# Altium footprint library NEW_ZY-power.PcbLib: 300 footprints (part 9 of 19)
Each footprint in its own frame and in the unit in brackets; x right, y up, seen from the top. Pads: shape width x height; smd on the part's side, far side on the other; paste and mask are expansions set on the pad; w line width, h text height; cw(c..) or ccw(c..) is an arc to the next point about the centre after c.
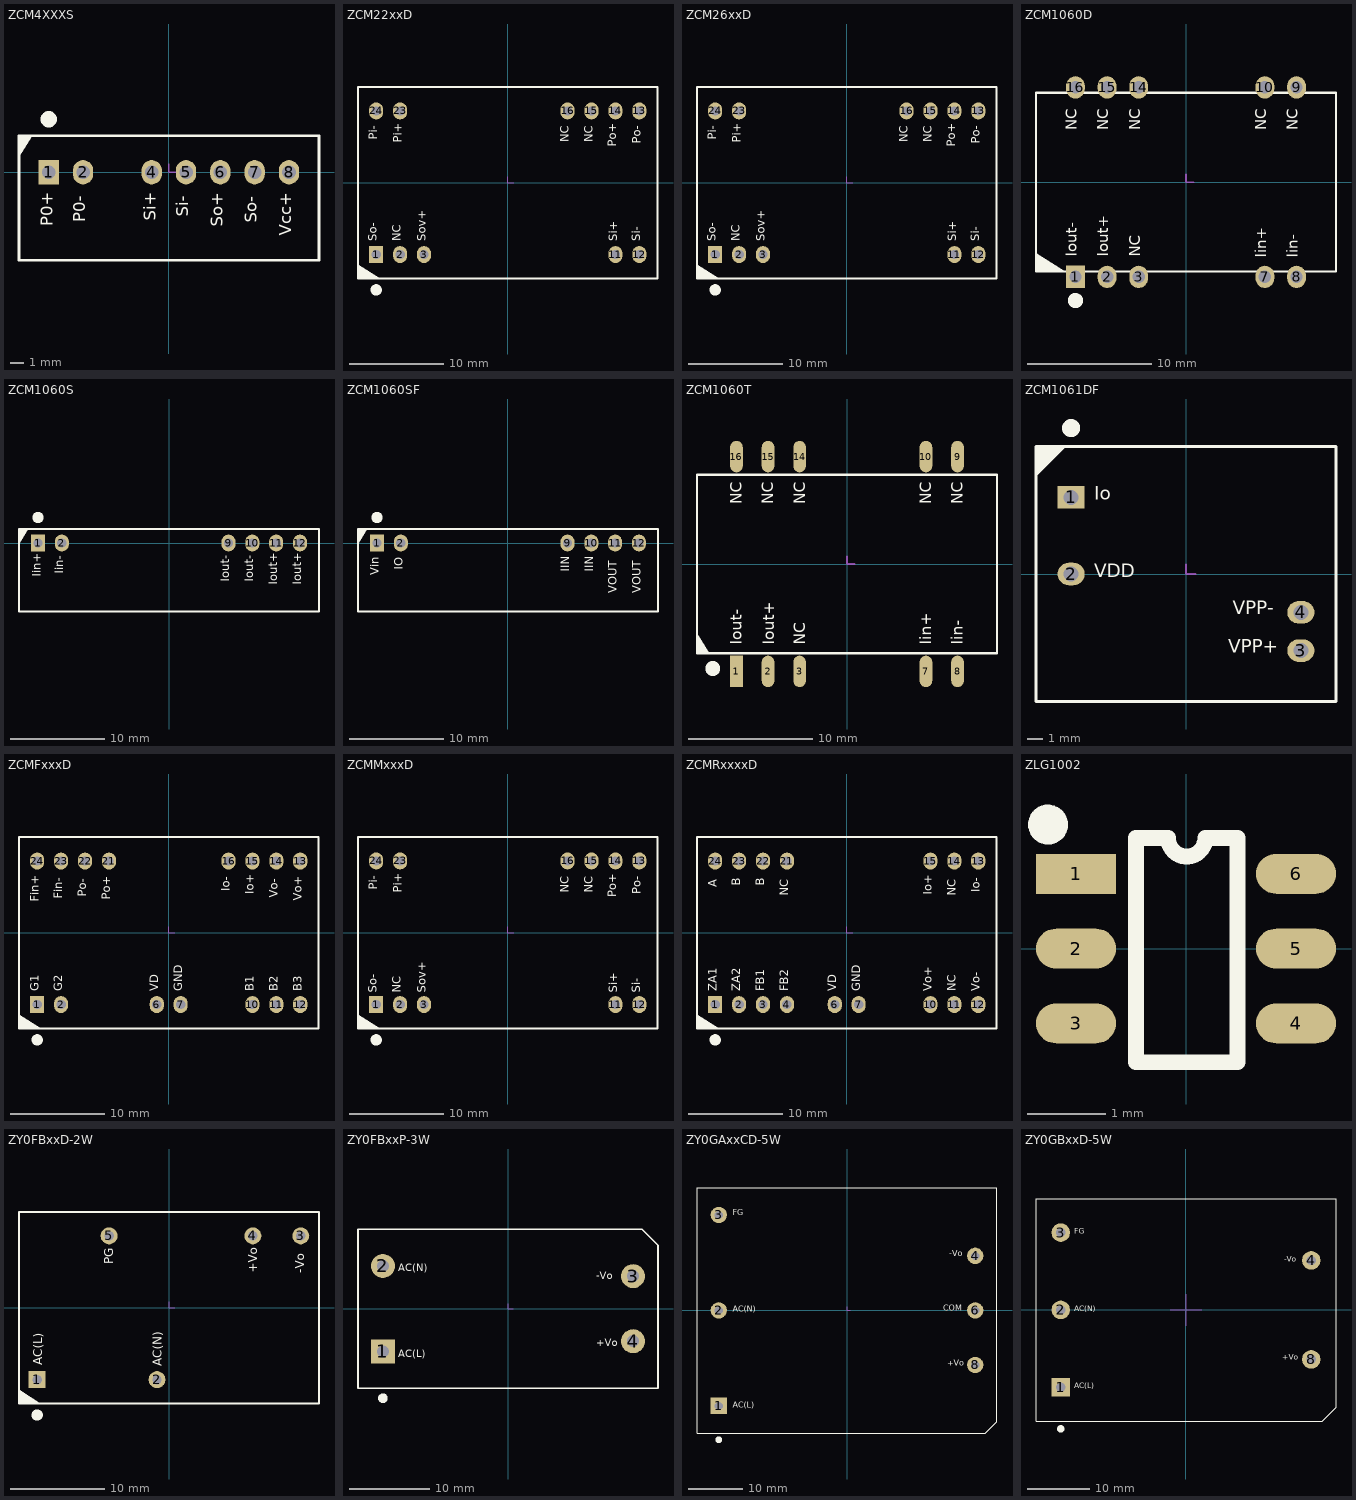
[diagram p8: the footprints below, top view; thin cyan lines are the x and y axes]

## ZCM4XXXS [mm]
pads (7):
  rect 1.5x1.8 hole 1: 1(-8.89,0)
  oval 1.5x1.8 hole 1: 2(-6.35,0) 4(-1.27,0) 5(1.27,0) 6(3.81,0) 7(6.35,0) 8(8.89,0)
Top Overlay:
  circle w1: c-8.89,3.925 r0.1
  region: -11.09,1.114 -11.09,2.7 -10.096,2.7
  lines w0.2: -11.09,-6.5 11.11,-6.5 11.11,2.7 -11.09,2.7 -11.09,-6.5
  text "Vcc+" at 9.357,-4.699 h1.52
  text "So-" at 6.817,-3.727 h1.52
  text "So+" at 4.277,-4.036 h1.52
  text "Si-" at 1.737,-3.273 h1.52
  text "Si+" at -0.676,-3.582 h1.52
  text "P0-" at -5.883,-3.684 h1.52
  text "P0+" at -8.296,-3.993 h1.52
Mechanical 15:
  lines w0.127: 0,0.635 0,0 0.635,0

## ZCM22xxD [mm]
height 9.5
pads (11):
  rect 1.5x1.8 hole 1: 1(-13.97,-7.62)
  oval 1.5x1.8 hole 1: 2(-11.43,-7.62) 3(-8.89,-7.62) 11(11.43,-7.62) 12(13.97,-7.62) 13(13.97,7.62) 14(11.43,7.62) 15(8.89,7.62) 16(6.35,7.62) 23(-11.43,7.62) 24(-13.97,7.62)
Top Overlay:
  circle w1: c-13.97,-11.375 r0.1
  region: -13.57,-10.15 -15.9,-10.15 -15.9,-8.69
  lines w0.2: -15.9,-10.15 15.9,-10.15 15.9,10.15 -15.9,10.15 -15.9,-10.15
  text "Po+" at 11.836,3.81 h1.52
  text "Pi+" at -10.922,4.265 h1.52
  text "Pi-" at -13.513,4.574 h1.52
  text "Sov+" at -8.382,-6.223 h1.52
  text "NC" at -11.049,-6.223 h1.52
  text "Si+" at 11.938,-6.223 h1.52
  text "So-" at -13.589,-6.223 h1.52
  text "Si-" at 14.402,-6.223 h1.52
  text "Po-" at 14.427,4.119 h1.52
  text "NC" at 9.322,4.281 h1.52
  text "NC" at 6.782,4.281 h1.52
Mechanical 15:
  lines w0.127: 0,0.635 0,0 0.635,0

## ZCM26xxD [mm]
height 9.5
pads (11):
  rect 1.5x1.8 hole 1: 1(-13.97,-7.62)
  oval 1.5x1.8 hole 1: 2(-11.43,-7.62) 3(-8.89,-7.62) 11(11.43,-7.62) 12(13.97,-7.62) 13(13.97,7.62) 14(11.43,7.62) 15(8.89,7.62) 16(6.35,7.62) 23(-11.43,7.62) 24(-13.97,7.62)
Top Overlay:
  circle w1: c-13.97,-11.375 r0.1
  region: -13.57,-10.15 -15.9,-10.15 -15.9,-8.69
  lines w0.2: -15.9,-10.15 -15.9,10.15 15.9,10.15 15.9,-10.15 -15.9,-10.15
  text "Si-" at 14.402,-6.223 h1.52
  text "So-" at -13.589,-6.223 h1.52
  text "Si+" at 11.938,-6.223 h1.52
  text "NC" at -11.049,-6.223 h1.52
  text "Sov+" at -8.382,-6.223 h1.52
  text "NC" at 6.782,4.281 h1.52
  text "NC" at 9.322,4.281 h1.52
  text "Po-" at 14.427,4.119 h1.52
  text "Pi-" at -13.513,4.574 h1.52
  text "Pi+" at -10.922,4.265 h1.52
  text "Po+" at 11.836,3.81 h1.52
Mechanical 15:
  lines w0.127: 0,0.635 0,0 0.635,0

## ZCM1060D [mm]
height 10
pads (10):
  rect 1.5x1.8 hole 1: 1(-8.89,-7.62)
  oval 1.5x1.8 hole 1: 2(-6.35,-7.62) 3(-3.81,-7.62) 7(6.35,-7.62) 8(8.89,-7.62) 9(8.89,7.62) 10(6.35,7.62) 14(-3.81,7.62) 15(-6.35,7.62) 16(-8.89,7.62)
Top Overlay:
  circle w1: c-8.89,-9.525 r0.1
  region: -9.735,-7.188 -12.065,-7.188 -12.065,-5.728
  lines w0.2: -12.065,-7.188 12.065,-7.188 12.065,7.188 -12.065,7.188 -12.065,-7.188
  text "Iin+" at 6.782,-6.071 h1.52
  text "Iin-" at 9.322,-6.071 h1.52
  text "Iout+" at -5.944,-5.994 h1.52
  text "NC" at -5.918,4.191 h1.52
  text "Iout-" at -8.484,-5.994 h1.52
  text "NC" at -8.458,4.191 h1.52
  text "NC" at -3.378,4.191 h1.52
  text "NC" at 6.782,4.191 h1.52
  text "NC" at 9.322,4.191 h1.52
  text "NC" at -3.353,-6.02 h1.52
Mechanical 15:
  lines w0.127: 0,0.635 0,0 0.635,0

## ZCM1060S [mm]
height 14.8
pads (6):
  rect 1.5x1.8 hole 1: 1(-13.97,0)
  oval 1.5x1.8 hole 1: 2(-11.43,0) 9(6.35,0) 10(8.89,0) 11(11.43,0) 12(13.97,0)
Top Overlay:
  circle w1: c-13.97,2.725 r0.1
  region: -16,-0.086 -16,1.5 -15.006,1.5
  lines w0.2: -16,-7.3 -16,1.5 16,1.5 16,-7.3 -16,-7.3
  text "Iin+" at -13.376,-3.611 h1.52
  text "Iin-" at -10.963,-3.302 h1.52
  text "Iout-" at 6.766,-4.136 h1.52
  text "Iout-" at 9.306,-4.136 h1.52
  text "Iout+" at 11.846,-4.445 h1.52
  text "Iout+" at 14.402,-4.445 h1.52

## ZCM1060SF [mm]
height 14.8
pads (6):
  rect 1.5x1.8 hole 1: 1(-13.97,0)
  oval 1.5x1.8 hole 1: 2(-11.43,0) 9(6.35,0) 10(8.89,0) 11(11.43,0) 12(13.97,0)
Top Overlay:
  circle w1: c-13.97,2.725 r0.1
  region: -16,-0.086 -16,1.5 -15.006,1.5
  lines w0.2: -16,-7.3 -16,1.5 16,1.5 16,-7.3 -16,-7.3
  text "Vin" at -13.46,-3.454 h1.52
  text "IO" at -10.92,-2.833 h1.52
  text "IIN" at 6.86,-3.086 h1.52
  text "IIN" at 9.4,-3.086 h1.52
  text "VOUT" at 11.94,-5.334 h1.52
  text "VOUT" at 14.48,-5.334 h1.52

## ZCM1060T [mil]
height 393.7
pads (10):
  rect 40x100 smd: 1(-350,-340)
  oval 40x100 smd: 2(-250,-340) 3(-150,-340) 7(250,-340) 8(350,-340) 9(350,340) 10(250,340) 14(-150,340) 15(-250,340) 16(-350,340)
Top Overlay:
  circle w39.37: c-425,-331.23 r3.94
  region: -475,-220.58 -475,-283 -435.88,-283
  lines w7.87: -475,-283 475,-283 475,283 -475,283 -475,-283
  text "Iin+" at 267,-255 h36
  text "Iin-" at 367,-255 h36
  text "Iout+" at -230,-255 h36
  text "NC" at -233,190 h36
  text "Iout-" at -334,-255 h36
  text "NC" at -333,190 h36
  text "NC" at -133,190 h36
  text "NC" at 267,190 h36
  text "NC" at 367,190 h36
  text "NC" at -132,-255 h36
Mechanical 15:
  lines w5: 0,25 0,0 25,0

## ZCM1061DF [mm]
height 7.05
pads (4):
  rect 1.8x1.5 hole 1: 1(-7.62,5.08)
  oval 1.8x1.5 hole 1: 2(-7.62,0) 3(7.62,-5.08) 4(7.62,-2.54)
Top Overlay:
  circle w1: c-7.62,9.677 r0.1
  region: -9.95,8.453 -7.975,8.452 -9.95,6.478
  lines w0.2: -9.95,-8.447 -9.95,8.453 9.95,8.453 9.95,-8.447 -9.95,-8.447
  text "VPP+" at 2.794,-5.532 h1.52
  text "VPP-" at 3.103,-2.966 h1.52
  text "Io" at -6.097,4.643 h1.52
  text "VDD" at -6.096,-0.508 h1.52
Mechanical 15:
  lines w0.127: 0,0.635 0,0 0.635,0

## ZCMFxxxD [mm]
pads (15):
  rect 1.5x1.8 hole 1: 1(-13.97,-7.62)
  oval 1.5x1.8 hole 1: 2(-11.43,-7.62) 6(-1.27,-7.62) 7(1.27,-7.62) 10(8.89,-7.62) 11(11.43,-7.62) 12(13.97,-7.62) 13(13.97,7.62) 14(11.43,7.62) 15(8.89,7.62) 16(6.35,7.62) 21(-6.35,7.62) 22(-8.89,7.62) 23(-11.43,7.62) 24(-13.97,7.62)
Top Overlay:
  circle w1: c-13.97,-11.375 r0.1
  region: -13.57,-10.15 -15.9,-10.15 -15.9,-8.69
  lines w0.2: -15.9,-10.15 -15.9,10.15 15.9,10.15 15.9,-10.15 -15.9,-10.15
  text "B3" at 14.437,-6.224 h1.52
  text "B2" at 11.897,-6.224 h1.52
  text "B1" at 9.357,-6.224 h1.52
  text "GND" at 1.737,-6.224 h1.52
  text "VD" at -0.803,-6.223 h1.52
  text "G2" at -10.963,-6.224 h1.52
  text "G1" at -13.503,-6.224 h1.52
  text "Vo+" at 14.437,3.422 h1.52
  text "Vo-" at 11.897,3.731 h1.52
  text "Io+" at 9.357,4.075 h1.52
  text "Io-" at 6.817,4.384 h1.52
  text "Po+" at -5.883,3.522 h1.52
  text "Po-" at -8.423,3.831 h1.52
  text "Fin-" at -10.963,3.611 h1.52
  text "Fin+" at -13.503,3.302 h1.52
Mechanical 15:
  lines w0.127: 0,0.635 0,0 0.635,0

## ZCMMxxxD [mm]
height 9.5
pads (11):
  rect 1.5x1.8 hole 1: 1(-13.97,-7.62)
  oval 1.5x1.8 hole 1: 2(-11.43,-7.62) 3(-8.89,-7.62) 11(11.43,-7.62) 12(13.97,-7.62) 13(13.97,7.62) 14(11.43,7.62) 15(8.89,7.62) 16(6.35,7.62) 23(-11.43,7.62) 24(-13.97,7.62)
Top Overlay:
  circle w1: c-13.97,-11.375 r0.1
  region: -13.57,-10.15 -15.9,-10.15 -15.9,-8.69
  lines w0.2: -15.9,-10.15 -15.9,10.15 15.9,10.15 15.9,-10.15 -15.9,-10.15
  text "NC" at 6.782,4.258 h1.52
  text "NC" at 9.322,4.258 h1.52
  text "Po-" at 14.427,4.096 h1.52
  text "Si-" at 14.402,-6.375 h1.52
  text "So-" at -13.589,-6.375 h1.52
  text "Si+" at 11.938,-6.375 h1.52
  text "NC" at -11.049,-6.375 h1.52
  text "Sov+" at -8.382,-6.375 h1.52
  text "Pi-" at -13.513,4.551 h1.52
  text "Pi+" at -10.922,4.242 h1.52
  text "Po+" at 11.836,3.787 h1.52
Mechanical 15:
  lines w0.127: 0,0.635 0,0 0.635,0

## ZCMRxxxxD [mm]
pads (16):
  rect 1.5x1.8 hole 1: 1(-13.97,-7.62)
  oval 1.5x1.8 hole 1: 2(-11.43,-7.62) 3(-8.89,-7.62) 4(-6.35,-7.62) 6(-1.27,-7.62) 7(1.27,-7.62) 10(8.89,-7.62) 11(11.43,-7.62) 12(13.97,-7.62) 13(13.97,7.62) 14(11.43,7.62) 15(8.89,7.62) 21(-6.35,7.62) 22(-8.89,7.62) 23(-11.43,7.62) 24(-13.97,7.62)
Top Overlay:
  circle w1: c-13.97,-11.375 r0.1
  region: -13.57,-10.15 -15.9,-10.15 -15.9,-8.69
  lines w0.2: -15.9,-10.15 15.9,-10.15 15.9,10.15 -15.9,10.15 -15.9,-10.15
  text "FB1" at -8.423,-6.223 h1.52
  text "FB2" at -5.883,-6.223 h1.52
  text "Vo-" at 14.437,-6.223 h1.52
  text "NC" at 11.897,-6.223 h1.52
  text "Vo+" at 9.357,-6.223 h1.52
  text "GND" at 1.737,-6.223 h1.52
  text "VD" at -0.803,-6.223 h1.52
  text "ZA2" at -10.963,-6.223 h1.52
  text "ZA1" at -13.503,-6.223 h1.52
  text "Io-" at 14.437,4.328 h1.52
  text "NC" at 11.897,3.937 h1.52
  text "Io+" at 9.357,4.019 h1.52
  text "NC" at -5.883,3.937 h1.52
  text "B" at -8.423,5.01 h1.52
  text "B" at -10.963,5.01 h1.52
  text "A" at -13.503,4.836 h1.52
Mechanical 15:
  lines w0.127: 0,0.635 0,0 0.635,0

## ZLG1002 [mil] "ZLG1002"
height 45.28
pads (6):
  rect 40x20 smd: 1(-55,37.4)
  oval 40x20 smd: 2(-55,0) 3(-55,-37.4) 4(55,-37.4) 5(55,0) 6(55,37.4)
Top Overlay:
  circle w10: c-69,62 r5
  lines w7.87: -25,55.4 -25,-56.8 25.7,-56.8 25.7,55.4 ; -9,55.4 ccw(c0.35,55.4) 9.7,55.4
  lines w8: -25,55.4 -9,55.4 ; 9.7,55.4 25.7,55.4
3D body: height 42.61, standoff -0.39, extent -48.5,-55 47,55

## ZY0FBxxD-2W [mm]
height 10.5
pads (5):
  rect 1.8x1.8 hole 1: 1(-13.97,-7.62)
  round 1.8 hole 1: 2(-1.27,-7.62) 3(13.97,7.62) 4(8.89,7.62) 5(-6.35,7.62)
Top Overlay:
  circle w1: c-13.97,-11.375 r0.1
  region: -13.57,-10.15 -15.9,-10.15 -15.9,-8.69
  lines w0.2: -15.9,-10.15 15.9,-10.15 15.9,10.15 -15.9,10.15 -15.9,-10.15
  text "AC(L)" at -13.462,-6.071 h0.91
  text "+Vo" at 9.373,3.708 h0.91
  text "-Vo" at 14.351,3.683 h0.91
  text "AC(N)" at -0.787,-6.223 h0.91
  text "PG" at -5.893,4.597 h0.91
Mechanical 15:
  lines w0.127: 0,0.635 0,0 0.635,0

## ZY0FBxxP-3W [mm]
pads (4):
  rect 3x3 hole 1.5: 1(-15.621,-5.334)
  round 3 hole 1.5: 2(-15.621,5.334) 3(15.621,4.064) 4(15.621,-4.064)
Top Overlay:
  circle w1: c-15.621,-11.174 r0.1
  lines w0.2: -18.737,-9.949 -18.737,9.949 16.721,9.949 18.737,7.933 18.737,-9.949 -18.737,-9.949
  text "+Vo" at 11.049,-4.699 h0.91
  text "-Vo" at 11.049,3.683 h0.91
  text "AC(N)" at -13.716,4.699 h0.91
  text "AC(L)" at -13.716,-6.096 h0.91
Mechanical 15:
  lines w0.127: 0,0.635 0,0 0.635,0

## ZY0GAxxCD-5W [mm]
height 20.5
pads (6):
  rect 3x3 hole 1.5: 1(-23.5,-17.5)
  round 3 hole 1.5: 2(-23.5,0) 3(-23.5,17.5) 4(23.5,10) 6(23.5,0) 8(23.5,-10)
Top Overlay:
  circle w1: c-23.5,-23.725 r0.1
  lines w0.2: -27.5,-22.5 25.379,-22.5 27.5,-20.379 27.5,22.5 -27.5,22.5 -27.5,-22.5
  text "-Vo" at 18.768,9.601 h1.78
  text "COM" at 17.658,-0.457 h1.78
  text "+Vo" at 18.343,-10.541 h1.78
  text "FG" at -20.96,17.043 h1.78
  text "AC(N)" at -20.96,-0.572 h1.78
  text "AC(L)" at -20.96,-18.186 h1.78
Mechanical 15:
  lines w0.127: 0,0.635 0,0 0.635,0

## ZY0GBxxD-5W [mm] "120426 修改 by kong"
height 20
pads (5):
  rect 3x3 hole 1.5: 1(-20.25,-12.5)
  round 3 hole 1.5: 2(-20.25,0) 3(-20.25,12.5) 4(20.25,8) 8(20.25,-8)
Top Overlay:
  circle w1: c-20.25,-19.225 r0.1
  lines w0.2: 22.033,-18 -24.25,-18 -24.25,18 24.25,18 24.25,-15.773 22.033,-17.991
  text "AC(L)" at -18.091,-13.008 h1.52
  text "AC(N)" at -18.091,-0.562 h1.52
  text "FG" at -18.091,12.011 h1.52
  text "+Vo" at 15.551,-8.381 h1.52
  text "-Vo" at 15.863,7.439 h1.52
Mechanical 15:
  lines w0.152: -2.54,0 2.54,0 ; 0,-2.54 0,2.54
